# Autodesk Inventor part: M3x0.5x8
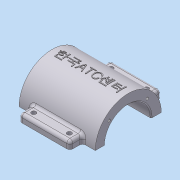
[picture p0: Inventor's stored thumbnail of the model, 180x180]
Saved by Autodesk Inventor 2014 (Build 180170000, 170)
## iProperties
Company: 한국ATC센터
Created: 2009-02
Part Number: M3x0.5x8
Document SubType Name: Modeling
Designer: KYOUNG IL JANG
Density: 2.71 g/cm^3
Mass: 199.244 g
Surface Area: 195.42 cm^2
Volume: 73.5219 cm^3
Material: 알루미늄-6061
Vendor: CBT Solutions
Appearance: 알루미늄 - 평지
Author: KYOUNG IL JANG
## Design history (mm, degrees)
sketch "스케치1"
  geometry: L1 (-45, 40)-(45, 40); L2 (45, 40)-(45, -40); L3 (45, -40)-(-45, -40); L4 (-45, -40)-(-45, 40); 3 further points
  constraints: 8 end point, 2 midpoint, 2 parallel, 1 horizontal, 1 horizontal alignment, 1 perpendicular, 1 vertical alignment
  dimensions: "d0" = 90 distance of L2.end L3.end; "d1" = 80 distance of L1.end L2.end
extrude "돌출1" new body sketch "스케치1" distance "d2" = 10; taper "d3" = 0 deg
sketch "스케치2"
  geometry: L1 (40, 0)-(-40, 0) reference; C1 r 32.5 at (0, 80); 2 further points
  constraints: 1 centre point, 1 midpoint, 1 vertical alignment
  dimensions: "d4" = 65 diameter of C1; "d5" = 80 distance from line of C1.centre L1
extrude "돌출2" join sketch "스케치2" stored distance "d6" = 75; taper "d7" = 0 deg
sketch "스케치3"
  geometry: L1 (-7.5, -20)-(7.5, -20); L2 (7.5, 20)-(-7.5, 20); A1 r 20 centre (7.5, 0) between (7.5, -20) and (7.5, 20); A2 r 20 centre (-7.5, 0) between (-7.5, 20) and (-7.5, -20); 2 further points
  constraints: 4 end point, 4 point on circle, 4 tangent, 2 centre point, 1 horizontal, 1 horizontal alignment, 1 midpoint, 1 parallel, 1 vertical alignment
  dimensions: "d8" = 20 radius of A2; "d9" = 55 dimension on A1 A2
extrude "돌출3" join sketch "스케치3" stored distance "d10" = 75; taper "d11" = 0 deg
fillet "모깎기1" dims "d12" = 10
sketch "스케치4"
  geometry: L1 (-45, 0)-(-45, 10) reference; L2 (37.5, 47.5)-(-37.5, 47.5) reference; L3 (-45, 10)-(-27.513, 47.5); 1 further point
  constraints: 2 end point, 1 point on line
  dimensions: "d13" = 25 deg angle of L3 L1
sketch "스케치5"
  geometry: L1 (-40, 0)-(-40, 10) reference; L2 (-40, 10)-(-22.912, 56.95); 2 further points
  constraints: 2 end point, 2 other
  dimensions: "d14" = 20 deg angle of L2 L1
feature "리브1" dims "d15" = 1, "d16" = 6, "d17" = 0
feature "리브2" dims "d18" = 1, "d19" = 6, "d20" = 0
fillet "모깎기2" dims "d21" = 3
fillet "모깎기3" dims "d22" = 3
fillet "모깎기4" dims "d23" = 3
fillet "모깎기5" dims "d24" = 3
fillet "모깎기6" dims "d25" = 3
fillet "모깎기7" dims "d26" = 3
fillet "모깎기8" dims "d27" = 3
sketch "스케치6"
  geometry: A1 r 10 centre (35, -30) between (35, -40) and (45, -30) reference; 1 further point
hole "구멍1" sketch "스케치6" at (35, -30) diameter "d28" = 10; stored, may be unused: countersink angle "d32" = 90 deg, drill point angle "d34" = 118 deg; dims "d29" = 6, "d30" = 4, "d31" = 2, "d33" = 8
hole "구멍2" diameter "d37" = 45; stored, may be unused: countersink angle "d41" = 90 deg, drill point angle "d43" = 118 deg; dims "d35" = 10, "d36" = 10, "d38" = 6, "d39" = 4, "d40" = 2, "d42" = 8
sketch "스케치7"
  geometry: C1 r 22.5 at (0, 0) reference; 2 further points
  dimensions: "d44" = 135 deg dimension on C1.centre point (-18.738, 18.738) point (80, 0); "d45" = 26.5 distance of point (-18.738, 18.738) C1.centre
hole "구멍3" sketch "스케치7" at (-18.738, 18.738) diameter "d46" = 2.459; stored, may be unused: countersink angle "d50" = 90 deg, drill point angle "d52" = 118 deg; dims "d47" = 8, "d48" = 4, "d49" = 2, "d51" = 10
node "작업 평면1"
chamfer "모따기1" distance "d69" = 1; stored, may be unused: second distance "d70" = 2, angle "d71" = 45 deg
sketch "스케치9"
  geometry: L1 (-31.623, 87.5)-(-45, 87.5); L2 (-45, 87.5)-(-45, 72.5); L3 (-45, 72.5)-(-31.623, 72.5); A1 r 32.5 centre (0, 80) between (-31.623, 87.5) and (-31.623, 72.5) reference; 1 further point
  constraints: 6 end point, 2 parallel, 2 point on circle, 1 horizontal, 1 perpendicular
  dimensions: "d73" = 15 distance of L1.end L2.end; "d74" = 45 distance from line of A1.centre L2
extrude "돌출5" join sketch "스케치9" stored distance "d75" = 50; taper "d76" = 0 deg
fillet "모깎기10" dims "d77" = 3
fillet "모깎기11" dims "d78" = 3
sketch "스케치10"
  geometry: L1 (100.378, 66.389)-(0, 66.389); L2 (0, 66.389)-(0, -76.978); L3 (0, -76.978)-(100.378, -76.978); L4 (100.378, -76.978)-(100.378, 66.389); C1 r 32.5 at (0, 0) reference; 1 further point
  constraints: 8 end point, 2 parallel, 1 horizontal, 1 perpendicular, 1 point on line
extrude "돌출6" cut sketch "스케치10" stored distance "d79" = 10; taper "d80" = 0 deg
sketch "스케치11"
  geometry: C1 r 1.621 at (4.5, 4) reference; C2 r 1.621 at (39.5, 4) reference; 1 further point
hole "구멍5" sketch "스케치11" at (39.5, 4), (4.5, 4) diameter "d81" = 4.5; stored, may be unused: countersink angle "d85" = 90 deg, drill point angle "d87" = 118 deg; dims "d82" = 6, "d83" = 4, "d84" = 2, "d86" = 8
node "작업 평면2"
sketch "스케치12"
  geometry: 2 further points
  constraints: 1 coincident, 1 other
feature "엠보싱1" sketch "스케치12" dims "d8" = 20, "d9" = 55, "d88" = 0.5, "d89" = 0
node "솔리드1"
mirror "대칭1"
mirror "대칭2"
mirror "대칭3"
mirror "대칭4"
pattern_circular "원형 패턴1" dims angle "d54" = 360 deg
mirror "대칭5"
mirror "대칭6"
mirror "대칭7"
node "참조1"
node "참조2"
other parameters: "d56" = -117
